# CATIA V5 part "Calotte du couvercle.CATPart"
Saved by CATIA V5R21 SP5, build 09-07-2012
Part number: Calotte du couvercle
Bounding box of the stored display mesh (mm): x -2075.97 to 2075.97, y -2073.827 to 2073.827, z 1222.17 to 2700
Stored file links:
  \\etu.ad.univ-lorraine.fr\bordron1\Documents\Parts EPR\Calotte du couvercle.CATPart
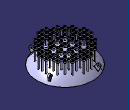
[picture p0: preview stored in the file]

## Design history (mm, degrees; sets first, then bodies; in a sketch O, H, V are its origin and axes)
AxisSystem1: origin (0, 0, 0), X (1, 0, 0), Y (0, 1, 0), Z (0, 0, 1)
AxisSystem2: origin (0, 0, 0), X (1, 0, 0), Y (0, 1, 0), Z (0, 0, 1)
Set1
  Plane1: type Offset, RefPlane xy-plane, Offset 2600
  Plane2: type Angle, RefPlane zx-plane, Direction edge [ZX plane of AxisSystem2 | YZ plane of AxisSystem2], Angle 20
Body1 (main body)
  Sketch1 on YZ plane of AxisSystem1, origin (0, 0, 0), H (0, 1, 0), V (0, 0, 1)
    arc A1 centre (0, 0) radius 2244 from (0, 2244) to (-1881.9768, 1222.17) ccw
    point P1 (0, 2244)
    arc A2 centre (0, 0) radius 2476 from (0, 2476) to (-2076.5483, 1348.5263) ccw
    point P3 (0, 2476)
    line L1 (0, 2476) -> (0, 2244)
    line L2 (-2076.5483, 1348.5263) -> (-1881.9768, 1222.17)
    reference projected line E1 through (0, 0) direction (0, 1) from edge [ZX plane of AxisSystem1 | YZ plane of AxisSystem1]
    radius A1 = 2244
    radius A2 = 2476
    angle L2 E1 = 57
    coincidence: P1 V, P3 V, L2 O
    vertical: L1 V
  Shaft1: profile Sketch1, axis edge [ZX plane of AxisSystem1 | YZ plane of AxisSystem1], angle 360
  Sketch2 on xy-plane, origin (0, 0, 0), H (1, 0, 0), V (0, 1, 0)
    circle A1 centre (0, 0) radius 0
    circle A2 centre (0, 0) radius 50
    circle A3 centre (280, 0) radius 50
    point P1 (280, 0)
    circle A4 centre (560, 0) radius 50
    point P2 (560, 0)
    circle A5 centre (1120, 0) radius 50
    point P3 (1120, 0)
    circle A6 centre (1400, 0) radius 50
    point P4 (1400, 0)
    circle A7 centre (1680, 0) radius 50
    point P5 (1680, 0)
    circle A8 centre (0, -280) radius 50
    point P6 (0, -280)
    circle A9 centre (0, -560) radius 50
    point P7 (0, -560)
    circle A10 centre (0, -1120) radius 50
    point P8 (0, -1120)
    circle A11 centre (0, -1400) radius 50
    point P9 (0, -1400)
    circle A12 centre (0, -1680) radius 50
    point P10 (0, -1680)
    circle A13 centre (560, -280) radius 50
    point P11 (560, -280)
    circle A14 centre (560, -560) radius 50
    circle A15 centre (280, -562.1859) radius 50
    point P13 (280, -562.1859)
    circle A16 centre (280, -1120) radius 50
    circle A17 centre (280, -842.1859) radius 50
    point P15 (280, -842.1859)
    circle A18 centre (1120, -280) radius 50
    circle A19 centre (840, -280) radius 50
    point P17 (840, -280)
    circle A20 centre (840, -842.1859) radius 50
    circle A21 centre (840, -1120) radius 50
    circle A22 centre (560, -1120) radius 50
    circle A23 centre (1120, -560) radius 50
    circle A24 centre (1120, -842.1859) radius 50
    circle A25 centre (280, -1400) radius 50
    circle A26 centre (560, -1400) radius 50
    circle A27 centre (280, -1680) radius 50
    circle A28 centre (840, -1400) radius 50
    circle A29 centre (1120, -1120) radius 50
    circle A30 centre (1400, -280) radius 50
    circle A31 centre (1680, -280) radius 50
    circle A32 centre (1400, -560) radius 50
    circle A33 centre (1400, -842.1859) radius 50
    circle A34 centre (0, 280) radius 50
    circle A35 centre (0, 560) radius 50
    circle A36 centre (0, 1120) radius 50
    circle A37 centre (0, 1400) radius 50
    circle A38 centre (0, 1680) radius 50
    circle A39 centre (-280, 0) radius 50
    circle A40 centre (-560, 0) radius 50
    circle A41 centre (-1120, 0) radius 50
    circle A42 centre (-1400, 0) radius 50
    circle A43 centre (-1680, 0) radius 50
    circle A44 centre (-560, -280) radius 50
    circle A45 centre (-560, -560) radius 50
    circle A46 centre (-280, -562.1859) radius 50
    circle A47 centre (-280, -1120) radius 50
    circle A48 centre (-280, -842.1859) radius 50
    circle A49 centre (-1120, -280) radius 50
    circle A50 centre (-840, -280) radius 50
    circle A51 centre (-840, -842.1859) radius 50
    circle A52 centre (-840, -1120) radius 50
    circle A53 centre (-560, -1120) radius 50
    circle A54 centre (-1120, -560) radius 50
    circle A55 centre (-1120, -842.1859) radius 50
    circle A56 centre (-280, -1400) radius 50
    circle A57 centre (-560, -1400) radius 50
    circle A58 centre (-280, -1680) radius 50
    circle A59 centre (-840, -1400) radius 50
    circle A60 centre (-1120, -1120) radius 50
    circle A61 centre (-1400, -280) radius 50
    circle A62 centre (-1680, -280) radius 50
    circle A63 centre (-1400, -560) radius 50
    circle A64 centre (-1400, -842.1859) radius 50
    circle A65 centre (560, 280) radius 50
    circle A66 centre (560, 560) radius 50
    circle A67 centre (280, 562.1859) radius 50
    circle A68 centre (280, 1120) radius 50
    circle A69 centre (280, 842.1859) radius 50
    circle A70 centre (1120, 280) radius 50
    circle A71 centre (840, 280) radius 50
    circle A72 centre (840, 842.1859) radius 50
    circle A73 centre (840, 1120) radius 50
    circle A74 centre (560, 1120) radius 50
    circle A75 centre (1120, 560) radius 50
    circle A76 centre (1120, 842.1859) radius 50
    circle A77 centre (280, 1400) radius 50
    circle A78 centre (560, 1400) radius 50
    circle A79 centre (280, 1680) radius 50
    circle A80 centre (840, 1400) radius 50
    circle A81 centre (1120, 1120) radius 50
    circle A82 centre (1400, 280) radius 50
    circle A83 centre (1680, 280) radius 50
    circle A84 centre (1400, 560) radius 50
    circle A85 centre (1400, 842.1859) radius 50
    circle A86 centre (-560, 280) radius 50
    circle A87 centre (-560, 560) radius 50
    circle A88 centre (-280, 562.1859) radius 50
    circle A89 centre (-280, 1120) radius 50
    circle A90 centre (-280, 842.1859) radius 50
    circle A91 centre (-1120, 280) radius 50
    circle A92 centre (-840, 280) radius 50
    circle A93 centre (-840, 842.1859) radius 50
    circle A94 centre (-840, 1120) radius 50
    circle A95 centre (-560, 1120) radius 50
    circle A96 centre (-1120, 560) radius 50
    circle A97 centre (-1120, 842.1859) radius 50
    circle A98 centre (-280, 1400) radius 50
    circle A99 centre (-560, 1400) radius 50
    circle A100 centre (-280, 1680) radius 50
    circle A101 centre (-840, 1400) radius 50
    circle A102 centre (-1120, 1120) radius 50
    circle A103 centre (-1400, 280) radius 50
    circle A104 centre (-1680, 280) radius 50
    circle A105 centre (-1400, 560) radius 50
    circle A106 centre (-1400, 842.1859) radius 50
    radius A2 = 50
    distance O P1 = 280
    distance P1 P2 = 280
    distance P3 P4 = 280
    distance P4 P5 = 280
    distance P2 P3 = 560
    radius A3 = 50
    radius A4 = 50
    radius A5 = 50
    radius A6 = 50
    radius A7 = 50
    distance P6 O = 280
    distance P6 P7 = 280
    radius A8 = 50
    radius A9 = 50
    distance P7 P8 = 560
    distance P8 P9 = 280
    distance P9 P10 = 280
    radius A10 = 50
    radius A11 = 50
    radius A12 = 50
    radius A13 = 50
    radius A14 = 50
    radius A15 = 50
    radius A16 = 50
    distance P15 P13 = 280
    radius A17 = 50
    distance P11 P17 = 280
    radius A19 = 50
    radius A18 = 50
    radius A20 = 50
    radius A21 = 50
    radius A22 = 50
    radius A24 = 50
    radius A23 = 50
    radius A25 = 50
    radius A27 = 50
    radius A26 = 50
    radius A28 = 50
    radius A29 = 50
    radius A33 = 50
    radius A30 = 50
    radius A32 = 50
    radius A31 = 50
    coincidence: P1 H, P2 H, P3 H, P4 H, P5 H, P6 V, P7 V, P8 V, P9 V, P10 V
    symmetry: A8 A34 H, A9 A35 H, A10 A36 H, A11 A37 H, A12 A38 H, A3 A39 V, A4 A40 V, A5 A41 V, A6 A42 V, A7 A43 V, A13 A44 V, A14 A45 V, A15 A46 V, A16 A47 V, A17 A48 V, A18 A49 V, A19 A50 V, A20 A51 V, A21 A52 V, A22 A53 V, A23 A54 V, A24 A55 V, A25 A56 V, A26 A57 V, A27 A58 V, A28 A59 V, A29 A60 V, A30 A61 V, A31 A62 V, A32 A63 V, A33 A64 V, A13 A65 H, A14 A66 H, A15 A67 H, A16 A68 H, A17 A69 H, A18 A70 H, A19 A71 H, A20 A72 H, A21 A73 H, A22 A74 H, A23 A75 H, A24 A76 H, A25 A77 H, A26 A78 H, A27 A79 H, A28 A80 H, A29 A81 H, A30 A82 H, A31 A83 H, A32 A84 H, A33 A85 H, A65 A86 V, A66 A87 V, A67 A88 V, A68 A89 V, A69 A90 V, A70 A91 V, A71 A92 V, A72 A93 V, A73 A94 V, A74 A95 V, A75 A96 V, A76 A97 V, A77 A98 V, A78 A99 V, A79 A100 V, A80 A101 V, A81 A102 V, A82 A103 V, A83 A104 V, A84 A105 V, A85 A106 V
  Pocket1: profile Sketch2, direction (0, 0, -1), through (limit type 6)
  Sketch3 on xy-plane, origin (0, 0, 0), H (1, 0, 0), V (0, 1, 0)
    circle A1 centre (0, 0) radius 0
    circle A2 centre (0, 0) radius 50
    circle A3 centre (280, 0) radius 50
    point P1 (280, 0)
    circle A4 centre (560, 0) radius 50
    point P2 (560, 0)
    circle A5 centre (1120, 0) radius 50
    point P3 (1120, 0)
    circle A6 centre (1400, 0) radius 50
    point P4 (1400, 0)
    circle A7 centre (1680, 0) radius 50
    point P5 (1680, 0)
    circle A8 centre (0, -280) radius 50
    point P6 (0, -280)
    circle A9 centre (0, -560) radius 50
    point P7 (0, -560)
    circle A10 centre (0, -1120) radius 50
    point P8 (0, -1120)
    circle A11 centre (0, -1400) radius 50
    point P9 (0, -1400)
    circle A12 centre (0, -1680) radius 50
    point P10 (0, -1680)
    circle A13 centre (560, -280) radius 50
    point P11 (560, -280)
    circle A14 centre (560, -560) radius 50
    circle A15 centre (280, -562.1859) radius 50
    point P13 (280, -562.1859)
    circle A16 centre (280, -1120) radius 50
    circle A17 centre (280, -842.1859) radius 50
    point P15 (280, -842.1859)
    circle A18 centre (1120, -280) radius 50
    circle A19 centre (840, -280) radius 50
    point P17 (840, -280)
    circle A20 centre (840, -842.1859) radius 50
    circle A21 centre (840, -1120) radius 50
    circle A22 centre (560, -1120) radius 50
    circle A23 centre (1120, -560) radius 50
    circle A24 centre (1120, -842.1859) radius 50
    circle A25 centre (280, -1400) radius 50
    circle A26 centre (560, -1400) radius 50
    circle A27 centre (280, -1680) radius 50
    circle A28 centre (840, -1400) radius 50
    circle A29 centre (1120, -1120) radius 50
    circle A30 centre (1400, -280) radius 50
    circle A31 centre (1680, -280) radius 50
    circle A32 centre (1400, -560) radius 50
    circle A33 centre (1400, -842.1859) radius 50
    circle A34 centre (0, 0) radius 30
    circle A35 centre (0, -280) radius 30
    circle A36 centre (280, 0) radius 30
    circle A37 centre (560, 0) radius 30
    circle A38 centre (560, -280) radius 30
    circle A39 centre (280, -562.1859) radius 30
    circle A40 centre (560, -560) radius 30
    circle A41 centre (0, -560) radius 30
    circle A42 centre (840, -280) radius 30
    circle A43 centre (1120, 0) radius 30
    circle A44 centre (1400, 0) radius 30
    circle A45 centre (1680, 0) radius 30
    circle A46 centre (1120, -280) radius 30
    circle A47 centre (1400, -280) radius 30
    circle A48 centre (1680, -280) radius 30
    circle A49 centre (1120, -560) radius 30
    circle A50 centre (1400, -560) radius 30
    circle A51 centre (1400, -842.1859) radius 30
    circle A52 centre (1120, -842.1859) radius 30
    circle A53 centre (840, -842.1859) radius 30
    circle A54 centre (1120, -1120) radius 30
    circle A55 centre (840, -1120) radius 30
    circle A56 centre (560, -1120) radius 30
    circle A57 centre (280, -842.1859) radius 30
    circle A58 centre (280, -1120) radius 30
    circle A59 centre (280, -1400) radius 30
    circle A60 centre (560, -1400) radius 30
    circle A61 centre (840, -1400) radius 30
    circle A62 centre (0, -1120) radius 30
    circle A63 centre (0, -1400) radius 30
    circle A64 centre (0, -1680) radius 30
    circle A65 centre (280, -1680) radius 30
    circle A66 centre (0, 280) radius 50
    circle A67 centre (0, 560) radius 50
    circle A68 centre (0, 1120) radius 50
    circle A69 centre (0, 1400) radius 50
    circle A70 centre (0, 1680) radius 50
    circle A71 centre (0, 280) radius 30
    circle A72 centre (0, 560) radius 30
    circle A73 centre (0, 1120) radius 30
    circle A74 centre (0, 1400) radius 30
    circle A75 centre (0, 1680) radius 30
    circle A76 centre (-280, 0) radius 50
    circle A77 centre (-560, 0) radius 50
    circle A78 centre (-1120, 0) radius 50
    circle A79 centre (-1400, 0) radius 50
    circle A80 centre (-1680, 0) radius 50
    circle A81 centre (-280, 0) radius 30
    circle A82 centre (-560, 0) radius 30
    circle A83 centre (-1120, 0) radius 30
    circle A84 centre (-1400, 0) radius 30
    circle A85 centre (-1680, 0) radius 30
    circle A86 centre (560, 280) radius 50
    circle A87 centre (560, 560) radius 50
    circle A88 centre (280, 562.1859) radius 50
    circle A89 centre (280, 1120) radius 50
    circle A90 centre (280, 842.1859) radius 50
    circle A91 centre (1120, 280) radius 50
    circle A92 centre (840, 280) radius 50
    circle A93 centre (840, 842.1859) radius 50
    circle A94 centre (840, 1120) radius 50
    circle A95 centre (560, 1120) radius 50
    circle A96 centre (1120, 560) radius 50
    circle A97 centre (1120, 842.1859) radius 50
    circle A98 centre (280, 1400) radius 50
    circle A99 centre (560, 1400) radius 50
    circle A100 centre (280, 1680) radius 50
    circle A101 centre (840, 1400) radius 50
    circle A102 centre (1120, 1120) radius 50
    circle A103 centre (1400, 280) radius 50
    circle A104 centre (1680, 280) radius 50
    circle A105 centre (1400, 560) radius 50
    circle A106 centre (1400, 842.1859) radius 50
    circle A107 centre (560, 280) radius 30
    circle A108 centre (280, 562.1859) radius 30
    circle A109 centre (560, 560) radius 30
    circle A110 centre (840, 280) radius 30
    circle A111 centre (1120, 280) radius 30
    circle A112 centre (1400, 280) radius 30
    circle A113 centre (1680, 280) radius 30
    circle A114 centre (1120, 560) radius 30
    circle A115 centre (1400, 560) radius 30
    circle A116 centre (1400, 842.1859) radius 30
    circle A117 centre (1120, 842.1859) radius 30
    circle A118 centre (840, 842.1859) radius 30
    circle A119 centre (1120, 1120) radius 30
    circle A120 centre (840, 1120) radius 30
    circle A121 centre (560, 1120) radius 30
    circle A122 centre (280, 842.1859) radius 30
    circle A123 centre (280, 1120) radius 30
    circle A124 centre (280, 1400) radius 30
    circle A125 centre (560, 1400) radius 30
    circle A126 centre (840, 1400) radius 30
    circle A127 centre (280, 1680) radius 30
    circle A128 centre (-560, -280) radius 50
    circle A129 centre (-560, -560) radius 50
    circle A130 centre (-280, -562.1859) radius 50
    circle A131 centre (-280, -1120) radius 50
    circle A132 centre (-280, -842.1859) radius 50
    circle A133 centre (-1120, -280) radius 50
    circle A134 centre (-840, -280) radius 50
    circle A135 centre (-840, -842.1859) radius 50
    circle A136 centre (-840, -1120) radius 50
    circle A137 centre (-560, -1120) radius 50
    circle A138 centre (-1120, -560) radius 50
    circle A139 centre (-1120, -842.1859) radius 50
    circle A140 centre (-280, -1400) radius 50
    circle A141 centre (-560, -1400) radius 50
    circle A142 centre (-280, -1680) radius 50
    circle A143 centre (-840, -1400) radius 50
    circle A144 centre (-1120, -1120) radius 50
    circle A145 centre (-1400, -280) radius 50
    circle A146 centre (-1680, -280) radius 50
    circle A147 centre (-1400, -560) radius 50
    circle A148 centre (-1400, -842.1859) radius 50
    circle A149 centre (-560, -280) radius 30
    circle A150 centre (-280, -562.1859) radius 30
    circle A151 centre (-560, -560) radius 30
    circle A152 centre (-840, -280) radius 30
    circle A153 centre (-1120, -280) radius 30
    circle A154 centre (-1400, -280) radius 30
    circle A155 centre (-1680, -280) radius 30
    circle A156 centre (-1120, -560) radius 30
    circle A157 centre (-1400, -560) radius 30
    circle A158 centre (-1400, -842.1859) radius 30
    circle A159 centre (-1120, -842.1859) radius 30
    circle A160 centre (-840, -842.1859) radius 30
    circle A161 centre (-1120, -1120) radius 30
    circle A162 centre (-840, -1120) radius 30
    circle A163 centre (-560, -1120) radius 30
    circle A164 centre (-280, -842.1859) radius 30
    circle A165 centre (-280, -1120) radius 30
    circle A166 centre (-280, -1400) radius 30
    circle A167 centre (-560, -1400) radius 30
    circle A168 centre (-840, -1400) radius 30
    circle A169 centre (-280, -1680) radius 30
    circle A170 centre (-560, 280) radius 50
    circle A171 centre (-560, 560) radius 50
    circle A172 centre (-280, 562.1859) radius 50
    circle A173 centre (-280, 1120) radius 50
    circle A174 centre (-280, 842.1859) radius 50
    circle A175 centre (-1120, 280) radius 50
    circle A176 centre (-840, 280) radius 50
    circle A177 centre (-840, 842.1859) radius 50
    circle A178 centre (-840, 1120) radius 50
    circle A179 centre (-560, 1120) radius 50
    circle A180 centre (-1120, 560) radius 50
    circle A181 centre (-1120, 842.1859) radius 50
    circle A182 centre (-280, 1400) radius 50
    circle A183 centre (-560, 1400) radius 50
    circle A184 centre (-280, 1680) radius 50
    circle A185 centre (-840, 1400) radius 50
    circle A186 centre (-1120, 1120) radius 50
    circle A187 centre (-1400, 280) radius 50
    circle A188 centre (-1680, 280) radius 50
    circle A189 centre (-1400, 560) radius 50
    circle A190 centre (-1400, 842.1859) radius 50
    circle A191 centre (-560, 280) radius 30
    circle A192 centre (-280, 562.1859) radius 30
    circle A193 centre (-560, 560) radius 30
    circle A194 centre (-840, 280) radius 30
    circle A195 centre (-1120, 280) radius 30
    circle A196 centre (-1400, 280) radius 30
    circle A197 centre (-1680, 280) radius 30
    circle A198 centre (-1120, 560) radius 30
    circle A199 centre (-1400, 560) radius 30
    circle A200 centre (-1400, 842.1859) radius 30
    circle A201 centre (-1120, 842.1859) radius 30
    circle A202 centre (-840, 842.1859) radius 30
    circle A203 centre (-1120, 1120) radius 30
    circle A204 centre (-840, 1120) radius 30
    circle A205 centre (-560, 1120) radius 30
    circle A206 centre (-280, 842.1859) radius 30
    circle A207 centre (-280, 1120) radius 30
    circle A208 centre (-280, 1400) radius 30
    circle A209 centre (-560, 1400) radius 30
    circle A210 centre (-840, 1400) radius 30
    circle A211 centre (-280, 1680) radius 30
    radius A2 = 50
    distance O P1 = 280
    distance P1 P2 = 280
    distance P3 P4 = 280
    distance P4 P5 = 280
    distance P2 P3 = 560
    radius A3 = 50
    radius A4 = 50
    radius A5 = 50
    radius A6 = 50
    radius A7 = 50
    distance P6 O = 280
    distance P6 P7 = 280
    radius A8 = 50
    radius A9 = 50
    distance P7 P8 = 560
    distance P8 P9 = 280
    distance P9 P10 = 280
    radius A10 = 50
    radius A11 = 50
    radius A12 = 50
    radius A13 = 50
    radius A14 = 50
    radius A15 = 50
    radius A16 = 50
    distance P15 P13 = 280
    radius A17 = 50
    distance P11 P17 = 280
    radius A19 = 50
    radius A18 = 50
    radius A20 = 50
    radius A21 = 50
    radius A22 = 50
    radius A24 = 50
    radius A23 = 50
    radius A25 = 50
    radius A27 = 50
    radius A26 = 50
    radius A28 = 50
    radius A29 = 50
    radius A33 = 50
    radius A30 = 50
    radius A32 = 50
    radius A31 = 50
    radius A34 = 30
    radius A36 = 30
    radius A37 = 30
    radius A35 = 30
    radius A38 = 30
    radius A41 = 30
    radius A39 = 30
    radius A40 = 30
    radius A42 = 30
    radius A46 = 30
    radius A43 = 30
    radius A44 = 30
    radius A45 = 30
    radius A48 = 30
    radius A47 = 30
    radius A50 = 30
    radius A49 = 30
    radius A51 = 30
    radius A52 = 30
    radius A53 = 30
    radius A54 = 30
    radius A55 = 30
    radius A56 = 30
    radius A61 = 30
    radius A57 = 30
    radius A58 = 30
    radius A60 = 30
    radius A62 = 30
    radius A63 = 30
    radius A59 = 30
    radius A64 = 30
    radius A65 = 30
    coincidence: P1 H, P2 H, P3 H, P4 H, P5 H, P6 V, P7 V, P8 V, P9 V, P10 V
    symmetry: A8 A66 H, A9 A67 H, A10 A68 H, A11 A69 H, A12 A70 H, A35 A71 H, A41 A72 H, A62 A73 H, A63 A74 H, A64 A75 H, A3 A76 V, A4 A77 V, A5 A78 V, A6 A79 V, A7 A80 V, A36 A81 V, A37 A82 V, A43 A83 V, A44 A84 V, A45 A85 V, A13 A86 H, A14 A87 H, A15 A88 H, A16 A89 H, A17 A90 H, A18 A91 H, A19 A92 H, A20 A93 H, A21 A94 H, A22 A95 H, A23 A96 H, A24 A97 H, A25 A98 H, A26 A99 H, A27 A100 H, A28 A101 H, A29 A102 H, A30 A103 H, A31 A104 H, A32 A105 H, A33 A106 H, A38 A107 H, A39 A108 H, A40 A109 H, A42 A110 H, A46 A111 H, A47 A112 H, A48 A113 H, A49 A114 H, A50 A115 H, A51 A116 H, A52 A117 H, A53 A118 H, A54 A119 H, A55 A120 H, A56 A121 H, A57 A122 H, A58 A123 H, A59 A124 H, A60 A125 H, A61 A126 H, A65 A127 H, A13 A128 V, A14 A129 V, A15 A130 V, A16 A131 V, A17 A132 V, A18 A133 V, A19 A134 V, A20 A135 V, A21 A136 V, A22 A137 V, A23 A138 V, A24 A139 V, A25 A140 V, A26 A141 V, A27 A142 V, A28 A143 V, A29 A144 V, A30 A145 V, A31 A146 V, A32 A147 V, A33 A148 V, A38 A149 V, A39 A150 V, A40 A151 V, A42 A152 V, A46 A153 V, A47 A154 V, A48 A155 V, A49 A156 V, A50 A157 V, A51 A158 V, A52 A159 V, A53 A160 V, A54 A161 V, A55 A162 V, A56 A163 V, A57 A164 V, A58 A165 V, A59 A166 V, A60 A167 V, A61 A168 V, A65 A169 V, A86 A170 V, A87 A171 V, A88 A172 V, A89 A173 V, A90 A174 V, A91 A175 V, A92 A176 V, A93 A177 V, A94 A178 V, A95 A179 V, A96 A180 V, A97 A181 V, A98 A182 V, A99 A183 V, A100 A184 V, A101 A185 V, A102 A186 V, A103 A187 V, A104 A188 V, A105 A189 V, A106 A190 V, A107 A191 V, A108 A192 V, A109 A193 V, A110 A194 V, A111 A195 V, A112 A196 V, A113 A197 V, A114 A198 V, A115 A199 V, A116 A200 V, A117 A201 V, A118 A202 V, A119 A203 V, A120 A204 V, A121 A205 V, A122 A206 V, A123 A207 V, A124 A208 V, A125 A209 V, A126 A210 V, A127 A211 V
  Pad1: profile Sketch3, direction (0, 0, 1), up to Plane1, opposite side length -1000
  Sketch4 on YZ plane of AxisSystem1, origin (0, 0, 0), H (0, 1, 0), V (0, 0, 1)
    point P1 (0, 0)
    point P2 (0, 826.3739)
    arc A1 centre (0, 0) radius 2144 from (0, 2144) to (-1978.3433, 826.3739) ccw
    point P3 (0, 2144)
    line L1 (0, 826.3739) -> (0, 2144)
    line L2 (0, 826.3739) -> (-1978.3433, 826.3739)
    radius A1 = 2144
    coincidence: P1 V, P2 V, P3 V, P1 O
    vertical: L1 V
    horizontal: L2 H
  Groove1: profile Sketch4, axis Sketch4.V, angle 360
  Sketch5 on Plane1, origin (0, 0, 2600), H (1, 0, 0), V (0, 1, 0)
    circle A1 centre (0, 0) radius 0
    circle A2 centre (0, 0) radius 50
    circle A3 centre (280, 0) radius 50
    point P1 (280, 0)
    circle A4 centre (560, 0) radius 50
    point P2 (560, 0)
    circle A5 centre (1120, 0) radius 50
    point P3 (1120, 0)
    circle A6 centre (1400, 0) radius 50
    point P4 (1400, 0)
    circle A7 centre (1680, 0) radius 50
    point P5 (1680, 0)
    circle A8 centre (0, -280) radius 50
    point P6 (0, -280)
    circle A9 centre (0, -560) radius 50
    point P7 (0, -560)
    circle A10 centre (0, -1120) radius 50
    point P8 (0, -1120)
    circle A11 centre (0, -1400) radius 50
    point P9 (0, -1400)
    circle A12 centre (0, -1680) radius 50
    point P10 (0, -1680)
    circle A13 centre (560, -280) radius 50
    point P11 (560, -280)
    circle A14 centre (560, -560) radius 50
    circle A15 centre (280, -562.1859) radius 50
    point P13 (280, -562.1859)
    circle A16 centre (280, -1120) radius 50
    circle A17 centre (280, -842.1859) radius 50
    point P15 (280, -842.1859)
    circle A18 centre (1120, -280) radius 50
    circle A19 centre (840, -280) radius 50
    point P17 (840, -280)
    circle A20 centre (840, -842.1859) radius 50
    circle A21 centre (840, -1120) radius 50
    circle A22 centre (560, -1120) radius 50
    circle A23 centre (1120, -560) radius 50
    circle A24 centre (1120, -842.1859) radius 50
    circle A25 centre (280, -1400) radius 50
    circle A26 centre (560, -1400) radius 50
    circle A27 centre (280, -1680) radius 50
    circle A28 centre (840, -1400) radius 50
    circle A29 centre (1120, -1120) radius 50
    circle A30 centre (1400, -280) radius 50
    circle A31 centre (1680, -280) radius 50
    circle A32 centre (1400, -560) radius 50
    circle A33 centre (1400, -842.1859) radius 50
    circle A34 centre (0, 0) radius 100
    circle A35 centre (280, 0) radius 100
    circle A36 centre (560, 0) radius 100
    circle A37 centre (0, -280) radius 100
    circle A38 centre (560, -280) radius 100
    circle A39 centre (840, -280) radius 100
    circle A40 centre (0, -560) radius 100
    circle A41 centre (280, -562.1859) radius 100
    circle A42 centre (560, -560) radius 100
    circle A43 centre (1120, 0) radius 100
    circle A44 centre (1400, 0) radius 100
    circle A45 centre (1680, 0) radius 100
    circle A46 centre (1680, -280) radius 100
    circle A47 centre (1400, -280) radius 100
    circle A48 centre (1120, -280) radius 100
    circle A49 centre (1400, -560) radius 100
    circle A50 centre (1120, -560) radius 100
    circle A51 centre (1400, -842.1859) radius 100
    circle A52 centre (1120, -842.1859) radius 100
    circle A53 centre (840, -842.1859) radius 100
    circle A54 centre (1120, -1120) radius 100
    circle A55 centre (840, -1120) radius 100
    circle A56 centre (560, -1120) radius 100
    circle A57 centre (840, -1400) radius 100
    circle A58 centre (560, -1400) radius 100
    circle A59 centre (280, -842.1859) radius 100
    circle A60 centre (280, -1120) radius 100
    circle A61 centre (280, -1400) radius 100
    circle A62 centre (0, -1120) radius 100
    circle A63 centre (0, -1400) radius 100
    circle A64 centre (0, -1680) radius 100
    circle A65 centre (280, -1680) radius 100
    circle A66 centre (-280, 0) radius 50
    circle A67 centre (-560, 0) radius 50
    circle A68 centre (-1120, 0) radius 50
    circle A69 centre (-1400, 0) radius 50
    circle A70 centre (-1680, 0) radius 50
    circle A71 centre (-280, 0) radius 100
    circle A72 centre (-560, 0) radius 100
    circle A73 centre (-1120, 0) radius 100
    circle A74 centre (-1400, 0) radius 100
    circle A75 centre (-1680, 0) radius 100
    circle A76 centre (0, 280) radius 50
    circle A77 centre (0, 560) radius 50
    circle A78 centre (0, 1120) radius 50
    circle A79 centre (0, 1400) radius 50
    circle A80 centre (0, 1680) radius 50
    circle A81 centre (0, 280) radius 100
    circle A82 centre (0, 560) radius 100
    circle A83 centre (0, 1120) radius 100
    circle A84 centre (0, 1400) radius 100
    circle A85 centre (0, 1680) radius 100
    circle A86 centre (560, 280) radius 50
    circle A87 centre (560, 560) radius 50
    circle A88 centre (280, 562.1859) radius 50
    circle A89 centre (280, 1120) radius 50
    circle A90 centre (280, 842.1859) radius 50
    circle A91 centre (1120, 280) radius 50
    circle A92 centre (840, 280) radius 50
    circle A93 centre (840, 842.1859) radius 50
    circle A94 centre (840, 1120) radius 50
    circle A95 centre (560, 1120) radius 50
    circle A96 centre (1120, 560) radius 50
    circle A97 centre (1120, 842.1859) radius 50
    circle A98 centre (280, 1400) radius 50
    circle A99 centre (560, 1400) radius 50
    circle A100 centre (280, 1680) radius 50
    circle A101 centre (840, 1400) radius 50
    circle A102 centre (1120, 1120) radius 50
    circle A103 centre (1400, 280) radius 50
    circle A104 centre (1680, 280) radius 50
    circle A105 centre (1400, 560) radius 50
    circle A106 centre (1400, 842.1859) radius 50
    circle A107 centre (560, 280) radius 100
    circle A108 centre (840, 280) radius 100
    circle A109 centre (280, 562.1859) radius 100
    circle A110 centre (560, 560) radius 100
    circle A111 centre (1680, 280) radius 100
    circle A112 centre (1400, 280) radius 100
    circle A113 centre (1120, 280) radius 100
    circle A114 centre (1400, 560) radius 100
    circle A115 centre (1120, 560) radius 100
    circle A116 centre (1400, 842.1859) radius 100
    circle A117 centre (1120, 842.1859) radius 100
    circle A118 centre (840, 842.1859) radius 100
    circle A119 centre (1120, 1120) radius 100
    circle A120 centre (840, 1120) radius 100
    circle A121 centre (560, 1120) radius 100
    circle A122 centre (840, 1400) radius 100
    circle A123 centre (560, 1400) radius 100
    circle A124 centre (280, 842.1859) radius 100
    circle A125 centre (280, 1120) radius 100
    circle A126 centre (280, 1400) radius 100
    circle A127 centre (280, 1680) radius 100
    circle A128 centre (-560, -280) radius 50
    circle A129 centre (-560, -560) radius 50
    circle A130 centre (-280, -562.1859) radius 50
    circle A131 centre (-280, -1120) radius 50
    circle A132 centre (-280, -842.1859) radius 50
    circle A133 centre (-1120, -280) radius 50
    circle A134 centre (-840, -280) radius 50
    circle A135 centre (-840, -842.1859) radius 50
    circle A136 centre (-840, -1120) radius 50
    circle A137 centre (-560, -1120) radius 50
    circle A138 centre (-1120, -560) radius 50
    circle A139 centre (-1120, -842.1859) radius 50
    circle A140 centre (-280, -1400) radius 50
    circle A141 centre (-560, -1400) radius 50
    circle A142 centre (-280, -1680) radius 50
    circle A143 centre (-840, -1400) radius 50
    circle A144 centre (-1120, -1120) radius 50
    circle A145 centre (-1400, -280) radius 50
    circle A146 centre (-1680, -280) radius 50
    circle A147 centre (-1400, -560) radius 50
    circle A148 centre (-1400, -842.1859) radius 50
    circle A149 centre (-560, -280) radius 100
    circle A150 centre (-840, -280) radius 100
    circle A151 centre (-280, -562.1859) radius 100
    circle A152 centre (-560, -560) radius 100
    circle A153 centre (-1680, -280) radius 100
    circle A154 centre (-1400, -280) radius 100
    circle A155 centre (-1120, -280) radius 100
    circle A156 centre (-1400, -560) radius 100
    circle A157 centre (-1120, -560) radius 100
    circle A158 centre (-1400, -842.1859) radius 100
    circle A159 centre (-1120, -842.1859) radius 100
    circle A160 centre (-840, -842.1859) radius 100
    circle A161 centre (-1120, -1120) radius 100
    circle A162 centre (-840, -1120) radius 100
    circle A163 centre (-560, -1120) radius 100
    circle A164 centre (-840, -1400) radius 100
    circle A165 centre (-560, -1400) radius 100
    circle A166 centre (-280, -842.1859) radius 100
    circle A167 centre (-280, -1120) radius 100
    circle A168 centre (-280, -1400) radius 100
    circle A169 centre (-280, -1680) radius 100
    circle A170 centre (-560, 280) radius 50
    circle A171 centre (-560, 560) radius 50
    circle A172 centre (-280, 562.1859) radius 50
    circle A173 centre (-280, 1120) radius 50
    circle A174 centre (-280, 842.1859) radius 50
    circle A175 centre (-1120, 280) radius 50
    circle A176 centre (-840, 280) radius 50
    circle A177 centre (-840, 842.1859) radius 50
    circle A178 centre (-840, 1120) radius 50
    circle A179 centre (-560, 1120) radius 50
    circle A180 centre (-1120, 560) radius 50
    circle A181 centre (-1120, 842.1859) radius 50
    circle A182 centre (-280, 1400) radius 50
    circle A183 centre (-560, 1400) radius 50
    circle A184 centre (-280, 1680) radius 50
    circle A185 centre (-840, 1400) radius 50
    circle A186 centre (-1120, 1120) radius 50
    circle A187 centre (-1400, 280) radius 50
    circle A188 centre (-1680, 280) radius 50
    circle A189 centre (-1400, 560) radius 50
    circle A190 centre (-1400, 842.1859) radius 50
    circle A191 centre (-560, 280) radius 100
    circle A192 centre (-840, 280) radius 100
    circle A193 centre (-280, 562.1859) radius 100
    circle A194 centre (-560, 560) radius 100
    circle A195 centre (-1680, 280) radius 100
    circle A196 centre (-1400, 280) radius 100
    circle A197 centre (-1120, 280) radius 100
    circle A198 centre (-1400, 560) radius 100
    circle A199 centre (-1120, 560) radius 100
    circle A200 centre (-1400, 842.1859) radius 100
    circle A201 centre (-1120, 842.1859) radius 100
    circle A202 centre (-840, 842.1859) radius 100
    circle A203 centre (-1120, 1120) radius 100
    circle A204 centre (-840, 1120) radius 100
    circle A205 centre (-560, 1120) radius 100
    circle A206 centre (-840, 1400) radius 100
    circle A207 centre (-560, 1400) radius 100
    circle A208 centre (-280, 842.1859) radius 100
    circle A209 centre (-280, 1120) radius 100
    circle A210 centre (-280, 1400) radius 100
    circle A211 centre (-280, 1680) radius 100
    radius A2 = 50
    distance O P1 = 280
    distance P1 P2 = 280
    distance P3 P4 = 280
    distance P4 P5 = 280
    distance P2 P3 = 560
    radius A3 = 50
    radius A4 = 50
    radius A5 = 50
    radius A6 = 50
    radius A7 = 50
    distance P6 O = 280
    distance P6 P7 = 280
    radius A8 = 50
    radius A9 = 50
    distance P7 P8 = 560
    distance P8 P9 = 280
    distance P9 P10 = 280
    radius A10 = 50
    radius A11 = 50
    radius A12 = 50
    radius A13 = 50
    radius A14 = 50
    radius A15 = 50
    radius A16 = 50
    distance P15 P13 = 280
    radius A17 = 50
    distance P11 P17 = 280
    radius A19 = 50
    radius A18 = 50
    radius A20 = 50
    radius A21 = 50
    radius A22 = 50
    radius A24 = 50
    radius A23 = 50
    radius A25 = 50
    radius A27 = 50
    radius A26 = 50
    radius A28 = 50
    radius A29 = 50
    radius A33 = 50
    radius A30 = 50
    radius A32 = 50
    radius A31 = 50
    radius A34 = 100
    radius A35 = 100
    radius A36 = 100
    radius A43 = 100
    radius A44 = 100
    radius A45 = 100
    radius A37 = 100
    radius A38 = 100
    radius A39 = 100
    radius A40 = 100
    radius A41 = 100
    radius A42 = 100
    radius A48 = 100
    radius A47 = 100
    radius A46 = 100
    radius A50 = 100
    radius A49 = 100
    radius A53 = 100
    radius A52 = 100
    radius A51 = 100
    radius A54 = 100
    radius A55 = 100
    radius A56 = 100
    radius A59 = 100
    radius A57 = 100
    radius A58 = 100
    radius A61 = 100
    radius A60 = 100
    radius A65 = 100
    radius A62 = 100
    radius A63 = 100
    radius A64 = 100
    coincidence: P1 H, P2 H, P3 H, P4 H, P5 H, P6 V, P7 V, P8 V, P9 V, P10 V
    symmetry: A3 A66 V, A4 A67 V, A5 A68 V, A6 A69 V, A7 A70 V, A35 A71 V, A36 A72 V, A43 A73 V, A44 A74 V, A45 A75 V, A8 A76 H, A9 A77 H, A10 A78 H, A11 A79 H, A12 A80 H, A37 A81 H, A40 A82 H, A62 A83 H, A63 A84 H, A64 A85 H, A13 A86 H, A14 A87 H, A15 A88 H, A16 A89 H, A17 A90 H, A18 A91 H, A19 A92 H, A20 A93 H, A21 A94 H, A22 A95 H, A23 A96 H, A24 A97 H, A25 A98 H, A26 A99 H, A27 A100 H, A28 A101 H, A29 A102 H, A30 A103 H, A31 A104 H, A32 A105 H, A33 A106 H, A38 A107 H, A39 A108 H, A41 A109 H, A42 A110 H, A46 A111 H, A47 A112 H, A48 A113 H, A49 A114 H, A50 A115 H, A51 A116 H, A52 A117 H, A53 A118 H, A54 A119 H, A55 A120 H, A56 A121 H, A57 A122 H, A58 A123 H, A59 A124 H, A60 A125 H, A61 A126 H, A65 A127 H, A13 A128 V, A14 A129 V, A15 A130 V, A16 A131 V, A17 A132 V, A18 A133 V, A19 A134 V, A20 A135 V, A21 A136 V, A22 A137 V, A23 A138 V, A24 A139 V, A25 A140 V, A26 A141 V, A27 A142 V, A28 A143 V, A29 A144 V, A30 A145 V, A31 A146 V, A32 A147 V, A33 A148 V, A38 A149 V, A39 A150 V, A41 A151 V, A42 A152 V, A46 A153 V, A47 A154 V, A48 A155 V, A49 A156 V, A50 A157 V, A51 A158 V, A52 A159 V, A53 A160 V, A54 A161 V, A55 A162 V, A56 A163 V, A57 A164 V, A58 A165 V, A59 A166 V, A60 A167 V, A61 A168 V, A65 A169 V, A128 A170 H, A129 A171 H, A130 A172 H, A131 A173 H, A132 A174 H, A133 A175 H, A134 A176 H, A135 A177 H, A136 A178 H, A137 A179 H, A138 A180 H, A139 A181 H, A140 A182 H, A141 A183 H, A142 A184 H, A143 A185 H, A144 A186 H, A145 A187 H, A146 A188 H, A147 A189 H, A148 A190 H, A149 A191 H, A150 A192 H, A151 A193 H, A152 A194 H, A153 A195 H, A154 A196 H, A155 A197 H, A156 A198 H, A157 A199 H, A158 A200 H, A159 A201 H, A160 A202 H, A161 A203 H, A162 A204 H, A163 A205 H, A164 A206 H, A165 A207 H, A166 A208 H, A167 A209 H, A168 A210 H, A169 A211 H
  Pad2: profile Sketch5, direction (0, 0, 1), length 100
  Sketch6 on Plane2, origin (0, 0, 0), H (-0.9397, -0.342, 0), V (0, 0, 1)
    line L1 (-1942.3507, 1508.6322) -> (-2071.257, 1815.0149)
    line L2 (-1717.227, 1758.0888) -> (-1831.8941, 1939.8073)
    point P4 (-1831.8941, 1939.8073)
    circle A1 centre (-1946.4269, 1867.5355) radius 65
    arc A2 centre (-1946.4269, 1867.5355) radius 135.4288 from (-1831.8941, 1939.8073) to (-2071.257, 1815.0149) ccw
    point P6 (-1831.8941, 1939.8073)
    line L3 (-1717.227, 1758.0888) -> (-1942.3507, 1508.6322)
    radius A1 = 65
    tangency: A2 L2, L1 A2
    coincidence: P6 P4
  Pad3: profile Sketch6, direction (-0.342, 0.9397, 0), length 50, mirrored extent
  Fillet1: radius 20, on edge [end face of Pad3 | face of Shaft1 from Sketch1.A2]; edge [face of Shaft1 from Sketch1.A2 | face of Pad3 from Sketch6.L1]; edge [face of Shaft1 from Sketch1.A2 | start face of Pad3]; edge [face of Pad3 from Sketch6.L2 | face of Shaft1 from Sketch1.A2]
  CircPattern1: of Pad3, Sketch6, Fillet1, instances 4, angular step 90, axis from edge [ZX plane of AxisSystem2 | YZ plane of AxisSystem2]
